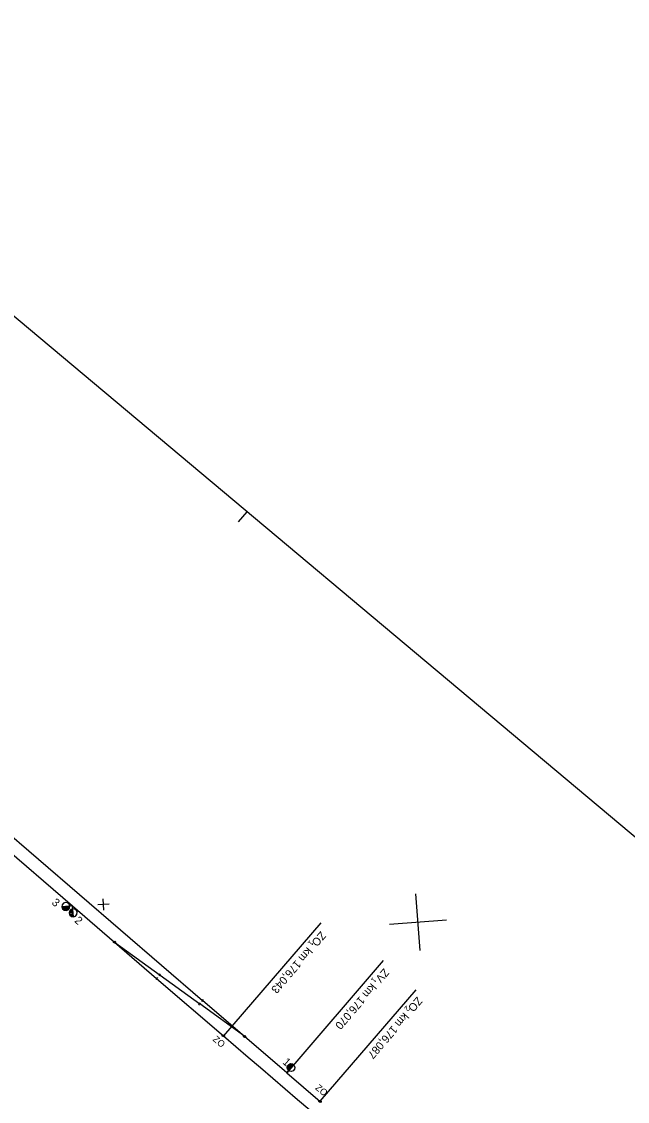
# Model space of a CAD drawing. Extents: x -473608 to -471381, y -1324122 to -1322275.
# Drawn here: x -472214.7 to -471987.7, y -1323575.9 to -1323171.1 of the extents above; entities that cross this region are included whole.
import ezdxf

# ---------------------------------------------------------------- set-up
doc = ezdxf.new("R2010")
doc.units = 0
for name, color, linetype in [('Level 1', 7, 'Continuous'), ('Level 11', 7, 'Continuous'), ('Level 61', 7, 'Continuous')]:
    doc.layers.add(name, color=color, linetype=linetype)

msp = doc.modelspace()

# ---------------------------------------------------------------- linework, layer by layer
at = {"layer": 'Level 1'}
for p, q in [((-472321.21, -1323387.89), (-472146.88, -1323537.97)), ((-472245.67, -1323459.53), (-472195.63, -1323502.6)), ((-472195.63, -1323502.6), (-472164.11, -1323529.74)), ((-472179.87, -1323516.17), (-472179.87, -1323516.17)), ((-472179.87, -1323516.17), (-472147.95, -1323539.33)), ((-472163.79, -1323529.36), (-472164.44, -1323530.11)), ((-472162.75, -1323527.98), (-472163.33, -1323528.78)), ((-472163.04, -1323528.38), (-472163.04, -1323528.38)), ((-472164.11, -1323529.74), (-472164.11, -1323529.74)), ((-472164.11, -1323529.74), (-472139.11, -1323551.26)), ((-472148.25, -1323539.73), (-472147.66, -1323538.92)), ((-472131.12, -1323551.54), (-472147.95, -1323539.33)), ((-472147.95, -1323539.33), (-472147.95, -1323539.33)), ((-472147.21, -1323538.35), (-472146.55, -1323537.59)), ((-472115.36, -1323565.11), (-472146.88, -1323537.97)), ((-472146.88, -1323537.97), (-472146.88, -1323537.97)), ((-472139.11, -1323551.26), (-472139.11, -1323551.26)), ((-472131.12, -1323551.54), (-472131.12, -1323551.54)), ((-472115.36, -1323565.11), (-472102.88, -1323575.85))]:
    msp.add_line(p, q, dxfattribs=at)
for points in [[(-472179.57, -1323516.43), (-472179.95, -1323516.56), (-472180.25, -1323516.3), (-472180.18, -1323515.91), (-472179.8, -1323515.78), (-472179.5, -1323516.03), (-472179.57, -1323516.43)], [(-472138.85, -1323550.96), (-472138.72, -1323551.33), (-472138.98, -1323551.64), (-472139.37, -1323551.56), (-472139.5, -1323551.19), (-472139.24, -1323550.88), (-472138.85, -1323550.96)], [(-472131.42, -1323551.28), (-472131.05, -1323551.15), (-472130.75, -1323551.41), (-472130.82, -1323551.8), (-472131.2, -1323551.93), (-472131.5, -1323551.67), (-472131.42, -1323551.28)], [(-472102.62, -1323575.55), (-472102.49, -1323575.92), (-472102.75, -1323576.23), (-472103.14, -1323576.15), (-472103.28, -1323575.77), (-472103.02, -1323575.47), (-472102.62, -1323575.55)]]:
    msp.add_lwpolyline(points, dxfattribs=at)
msp.add_arc((-465614.79, -1315972.79), 10000, 229.274753, 230.393272, dxfattribs=at)
at = {"layer": 'Level 11'}
for p, q in [((-472183.85, -1323504.18), (-472184.17, -1323499.92)), ((-472065.35, -1323519.33), (-472066.96, -1323498.02)), ((-472195.63, -1323502.6), (-472195.63, -1323502.6)), ((-472181.88, -1323501.89), (-472186.14, -1323502.21)), ((-472102.63, -1323508.94), (-472139.03, -1323551.25)), ((-472055.5, -1323507.88), (-472076.81, -1323509.48)), ((-472079.21, -1323523.08), (-472115.36, -1323565.11)), ((-472067.01, -1323534.05), (-472102.9, -1323575.76)), ((-472115.36, -1323565.11), (-472112.82, -1323562.08)), ((-472115.36, -1323565.11), (-472115.36, -1323565.11))]:
    msp.add_line(p, q, dxfattribs=at)
for points in [[(-472196.67, -1323502.69), (-472196.94, -1323501.96), (-472197.54, -1323501.46), (-472198.3, -1323501.32), (-472199.03, -1323501.59), (-472199.53, -1323502.19), (-472199.67, -1323502.95), (-472199.4, -1323503.68), (-472198.8, -1323504.18), (-472198.04, -1323504.31), (-472197.31, -1323504.05), (-472196.81, -1323503.45), (-472196.67, -1323502.69), (-472197.03, -1323502.86), (-472196.98, -1323503.5), (-472197.23, -1323503.8), (-472197.31, -1323502.96), (-472197.63, -1323502.95), (-472197.5, -1323503.97), (-472197.81, -1323504.1), (-472197.91, -1323502.97), (-472198.19, -1323503), (-472198.12, -1323504.16), (-472198.41, -1323504.12), (-472198.51, -1323502.99), (-472198.79, -1323503.02), (-472198.71, -1323504), (-472199.04, -1323503.78), (-472199.1, -1323503.08), (-472199.43, -1323503.07), (-472199.4, -1323503.42)], [(-472195.28, -1323506.61), (-472195.63, -1323502.6), (-472199.67, -1323502.95)], [(-472195.28, -1323506.63), (-472194.55, -1323506.36), (-472194.05, -1323505.77), (-472193.92, -1323504.96), (-472194.18, -1323504.27), (-472194.78, -1323503.77), (-472195.54, -1323503.64), (-472196.27, -1323503.91), (-472196.77, -1323504.5), (-472196.91, -1323505.22), (-472196.64, -1323505.99), (-472196.05, -1323506.49), (-472195.28, -1323506.63), (-472195.49, -1323506.31), (-472195.98, -1323506.35), (-472196.32, -1323506.06), (-472195.55, -1323506), (-472195.57, -1323505.72), (-472196.56, -1323505.8), (-472196.69, -1323505.49), (-472195.57, -1323505.4), (-472195.63, -1323505.08), (-472196.72, -1323505.21), (-472196.71, -1323504.89), (-472195.65, -1323504.8), (-472195.68, -1323504.52), (-472196.67, -1323504.6), (-472196.38, -1323504.26), (-472195.67, -1323504.2), (-472195.7, -1323503.92), (-472196.12, -1323503.95)], [(-472113.13, -1323561.83), (-472112.52, -1323562.34), (-472112.26, -1323563.09), (-472112.39, -1323563.82), (-472112.9, -1323564.43), (-472113.62, -1323564.69), (-472114.38, -1323564.56), (-472114.99, -1323564.05), (-472115.25, -1323563.32), (-472115.11, -1323562.56), (-472114.61, -1323561.97), (-472113.89, -1323561.7), (-472113.13, -1323561.83), (-472113.48, -1323561.86), (-472113.1, -1323562.18), (-472113.29, -1323562.41), (-472113.94, -1323561.86), (-472114.25, -1323562), (-472113.48, -1323562.64), (-472113.68, -1323562.87), (-472114.56, -1323562.13), (-472114.75, -1323562.36), (-472113.87, -1323563.1), (-472114.06, -1323563.33), (-472114.94, -1323562.59), (-472115.02, -1323562.91), (-472114.26, -1323563.56), (-472114.45, -1323563.79), (-472115.06, -1323563.27), (-472114.98, -1323563.73), (-472114.64, -1323564.02)]]:
    msp.add_lwpolyline(points, dxfattribs=at)
at = {"layer": 'Level 61'}
for p, q in [((-472612.76, -1322949.83), (-471486.68, -1323894.73)), ((-472133.37, -1323358.62), (-472130.16, -1323354.79))]:
    msp.add_line(p, q, dxfattribs=at)

# ---------------------------------------------------------------- texts
at = {"layer": 'Level 11'}
for s, height, rotation, p in [('3', 3, 319.3, (-472203.67, -1323501.69)), ('2', 3, 319.3, (-472195.16, -1323508.42)), ('ZO  km 176,043', 3, 229.3, (-472102.63, -1323511.91)), ('1', 2, 229.3, (-472106.62, -1323515.28)), ('ZV  km 176,070', 3, 229.3, (-472078.96, -1323525.77)), ('1', 2, 229.3, (-472082.96, -1323529.15)), ('ZO  km 176,087', 3, 229.3, (-472066.5, -1323536.42)), ('2', 2, 229.3, (-472070.49, -1323539.8)), ('ZO', 2.5, 320, (-472143.31, -1323552.9)), ('1', 3, 319.3, (-472117.13, -1323561.48)), ('ZO', 2.5, 320, (-472104.9, -1323571.1))]:
    msp.add_text(s, height=height, rotation=rotation, dxfattribs=at).set_placement(p)

doc.saveas('drawing.dxf')
